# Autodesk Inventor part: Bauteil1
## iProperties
Author: volkart
Shininess: 20.0
Angle Display Precision: 2
Document Length Units: 11269
Document Angle Units: 11283
Document Time Units: 11279
Document Mass Units: 11290
Document Length Units Precision: 3
Document Angle Units Precision: 2
Compacted: False
PropertySet Name: _Private Model Information
Created: 2004-01
Part Number: Bauteil1
Material: Standard
Document SubType Name: Modellieren
Designer: volkart
Control State: 0
Master: False
Checked Out: False
PropertySet Name: Design Tracking Control
Density: 0.0
Volumn: 0.0
Area: 0.0
PropertySet Name: Model Information
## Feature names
1. Drehung1 [Revolution]
2. Sweeping1
